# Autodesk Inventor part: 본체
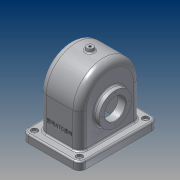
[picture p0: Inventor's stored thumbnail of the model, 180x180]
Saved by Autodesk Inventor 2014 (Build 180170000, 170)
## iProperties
Created: 2016-10
Part Number: 본체
Material: 알루미늄 6061
Document SubType Name: Modeling
Designer: USER
Density: 2.71 g/cm^3
Appearance: 알루미늄 - 평지
Author: USER
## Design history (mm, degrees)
sketch "스케치1"
  geometry: L1 (-55, -75)-(55, -75); L2 (55, -75)-(55, 75); L3 (55, 75)-(-55, 75); L4 (-55, 75)-(-55, -75); L5 (-55, -75)-(55, 75); L6 (55, -75)-(-55, 75); 3 further points
  constraints: 12 end point, 3 midpoint, 2 parallel, 1 coincident, 1 horizontal, 1 perpendicular
  dimensions: "d0" = 110 distance of L2.end L3.end; "d1" = 150 distance of L1.end L2.end
extrude "돌출1" new body sketch "스케치1" distance "d2" = 15; taper "d3" = 0 deg
fillet "모깎기1" dims "d4" = 12
sketch "스케치2"
  geometry: L1 (-58, 0)-(-58, 80); L2 (58, 80)-(58, 0); L3 (58, 0)-(-58, 0); A1 r 58 centre (0, 80) between (58, 80) and (-58, 80); 1 further point
  constraints: 6 end point, 2 point on circle, 2 tangent, 1 centre point, 1 midpoint, 1 parallel, 1 perpendicular, 1 vertical, 1 vertical alignment
  dimensions: "d5" = 80 distance from line of L3 A1.centre; "d6" = 58 radius of A1
extrude "돌출2" join sketch "스케치2" stored distance "d7" = 77; taper "d8" = 0 deg
fillet "모깎기2" dims "d9" = 13
sketch "스케치3"
  geometry: L1 (0, -63)-(0, 63) reference; C1 r 31 at (-65, 0); 2 further points
  constraints: 1 centre point, 1 horizontal alignment, 1 midpoint
  dimensions: "d10" = 62 diameter of C1; "d11" = 65 distance from line of L1 C1.centre
extrude "돌출3" join sketch "스케치3" distance "d12" = 10; taper "d13" = 0 deg
fillet "모깎기3" dims "d14" = 3
fillet "모깎기4" dims "d15" = 3
sketch "스케치4"
  geometry: L1 (63, 0)-(-63, 0) reference; L2 (-52, 0)-(-52, 80); L3 (52, 80)-(52, 0); A1 r 52 centre (0, 80) between (52, 80) and (-52, 80); A2 r 58 centre (0, 80) between (58, 80) and (-58, 80) reference; 1 further point
  constraints: 4 end point, 2 point on circle, 2 point on line, 2 tangent, 1 centre point, 1 concentric, 1 parallel, 1 perpendicular
  dimensions: "d16" = 52 radius of A1
extrude "돌출4" cut sketch "스케치4" stored distance "d17" = 67; taper "d18" = 0 deg
fillet "모깎기5" dims "d19" = 8
sketch "스케치5"
  geometry: L1 (33.5, 65)-(19.5, 65); L2 (19.5, 65)-(19.5, 93); L3 (19.5, 93)-(33.5, 104.747); L4 (33.5, 104.747)-(33.5, 65); L5 (-25.5, 0)-(25.5, 0) reference; L6 (33.5, 80)-(33.5, 0) reference; 1 further point
  constraints: 8 end point, 1 collinear, 1 horizontal, 1 parallel, 1 perpendicular
  dimensions: "d20" = 65 distance between parallel lines of L1 L5; "d21" = 50 deg angle of L2 L3; "d22" = 56 diameter of L2.end L1; "d23" = 14 distance of L1.start L1.end
revolve "회전1" sketch "스케치5" stored, may be unused: angle "d24" = 90 deg
fillet "모깎기6" dims "d25" = 3
sketch "스케치6"
  geometry: L1 (0, 63)-(0, -63) reference; C1 r 37.5 at (65, 0); 1 further point
  constraints: 1 centre point, 1 horizontal alignment
  dimensions: "d26" = 75 diameter of C1; "d27" = 65 distance from line of L1 C1.centre
extrude "돌출5" join sketch "스케치6" distance "d28" = 5; taper "d29" = 0 deg
fillet "모깎기7" dims "d30" = 3
hole "구멍1" diameter "d33" = 40; stored, may be unused: countersink angle "d37" = 90 deg, drill point angle "d39" = 118 deg; dims "d31" = 10, "d32" = 10, "d34" = 6, "d35" = 4, "d36" = 2, "d38" = 8
chamfer "모따기1" distance "d40" = 1; stored, may be unused: second distance "d41" = 2, angle "d42" = 45 deg
node "작업 평면1"
sketch "스케치7"
  geometry: C1 r 6 at (0, 0); 1 further point
  constraints: 1 centre point, 1 coincident
  dimensions: "d44" = 12 diameter of C1
extrude "돌출6" join sketch "스케치7" distance "d45" = 10; taper "d46" = 10 deg
fillet "모깎기8" dims "d47" = 3
hole "구멍2" diameter "d50" = 4.459; stored, may be unused: countersink angle "d54" = 90 deg, drill point angle "d56" = 118 deg; dims "d48" = 10, "d49" = 10, "d51" = 20, "d52" = 4, "d53" = 2, "d55" = 8
sketch "스케치8"
  geometry: C1 r 31 at (0, 0) reference; 2 further points
  constraints: 1 horizontal alignment
  dimensions: "d57" = 26 distance of C1.centre point (-26, 0)
hole "구멍3" sketch "스케치8" at (-26, 0) diameter "d58" = 2.459; stored, may be unused: countersink angle "d62" = 90 deg, drill point angle "d64" = 118 deg; dims "d59" = 6, "d60" = 4, "d61" = 2, "d63" = 8
sketch "스케치9"
  geometry: C1 r 37.5 at (0, 0) reference; 2 further points
  constraints: 1 horizontal alignment
  dimensions: "d68" = 29 distance of point (29, 0) C1.centre
hole "구멍4" sketch "스케치9" at (29, 0) diameter "d69" = 2.459; stored, may be unused: countersink angle "d73" = 90 deg, drill point angle "d75" = 118 deg; dims "d70" = 6, "d71" = 4, "d72" = 2, "d74" = 8
fillet "모깎기9" dims "d79" = 3
hole "구멍5" diameter "d82" = 5; stored, may be unused: countersink angle "d86" = 90 deg, drill point angle "d88" = 118 deg; dims "d80" = 10, "d81" = 10, "d83" = 6, "d84" = 12, "d85" = 5, "d87" = 8
sketch "스케치10" dims "d0" = 110, "d1" = 150
  geometry: L1 (-17.5, -80)-(68.5, -80) reference; L2 (-13, 0)-(-13, -62) reference; 2 further points
  constraints: 1 other
  dimensions: "d89" = 40 distance from line of L1 point (25.5, -40); "d90" = 38.5 distance from line of L2 point (25.5, -40)
feature "엠보싱1" sketch "스케치10" dims "d0" = 110, "d1" = 150, "d91" = 0.5, "d92" = 0
node "솔리드1"
pattern_circular "원형 패턴1" dims angle "d66" = 360 deg
pattern_circular "원형 패턴2" dims angle "d77" = 360 deg
mirror "대칭1"
mirror "대칭2"
other parameters: "d43" = 144
